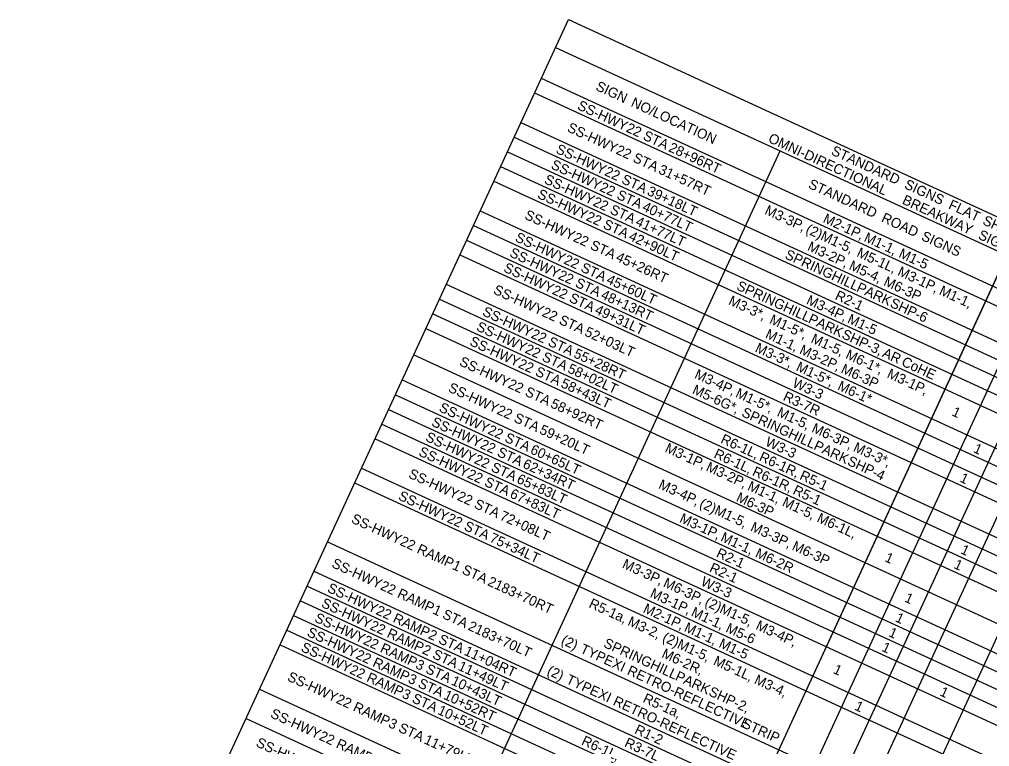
# Model space of a CAD drawing. Extents: x 627405 to 651306, y 367647 to 373471.
# Drawn here: x 650055.9 to 650493.4, y 373143.2 to 373471.4 of the extents above; entities that cross this region are included whole.
import ezdxf

# ---------------------------------------------------------------- set-up
doc = ezdxf.new("R2010")
doc.units = 0
doc.layers.add('Default', color=7, linetype='Continuous')

msp = doc.modelspace()

# ---------------------------------------------------------------- linework, layer by layer
at = {"layer": 'Default'}
for p, q in [((650055.92, 372934.12), (650303.5, 373471.4)), ((650303.5, 373471.4), (650303.5, 373471.4)), ((650303.5, 373471.4), (650631.25, 373320.37)), ((650297.69, 373458.78), (650625.43, 373307.75)), ((650291.26, 373444.83), (650619.01, 373293.81)), ((650291.26, 373444.83), (650597.76, 373303.6)), ((650288.2, 373438.19), (650615.95, 373287.16)), ((650282.08, 373424.91), (650609.83, 373273.88)), ((650279.02, 373418.27), (650606.77, 373267.24)), ((650157.2, 372887.45), (650398.97, 373412.11)), ((650275.96, 373411.63), (650603.71, 373260.6)), ((650272.9, 373404.99), (650600.65, 373253.96)), ((650269.84, 373398.35), (650597.59, 373247.32)), ((650263.72, 373385.06), (650591.46, 373234.03)), ((650260.66, 373378.42), (650588.4, 373227.39)), ((650257.6, 373371.78), (650585.34, 373220.75)), ((650254.54, 373365.14), (650582.28, 373214.11)), ((650259.47, 372840.32), (650501.24, 373364.98)), ((650259.47, 372840.32), (650498.03, 373358.01)), ((650248.42, 373351.86), (650576.16, 373200.83)), ((650275.41, 372832.97), (650513.97, 373350.66)), ((650245.35, 373345.22), (650573.1, 373194.19)), ((650288.03, 372827.16), (650526.59, 373344.85)), ((650242.29, 373338.57), (650570.04, 373187.54)), ((650300.65, 372821.34), (650539.21, 373339.03)), ((650239.23, 373331.93), (650566.98, 373180.9)), ((650321.24, 372811.86), (650559.79, 373329.55)), ((650233.73, 373319.98), (650561.47, 373168.95)), ((650228.52, 373308.69), (650556.27, 373157.66)), ((650225.46, 373302.05), (650553.21, 373151.02)), ((650222.4, 373295.41), (650550.15, 373144.38)), ((650219.34, 373288.76), (650547.09, 373137.74)), ((650216.28, 373282.12), (650544.03, 373131.09)), ((650210.16, 373268.84), (650537.91, 373117.81)), ((650207.1, 373262.2), (650534.85, 373111.17)), ((650194.86, 373235.63), (650522.61, 373084.6)), ((650188.74, 373222.35), (650516.49, 373071.32)), ((650185.68, 373215.71), (650513.43, 373064.68)), ((650182.62, 373209.07), (650510.37, 373058.04)), ((650179.56, 373202.43), (650507.3, 373051.4)), ((650176.5, 373195.79), (650504.24, 373044.76)), ((650173.44, 373189.14), (650501.18, 373038.12)), ((650164.26, 373169.22), (650492, 373018.19)), ((650158.13, 373155.94), (650485.88, 373004.91))]:
    msp.add_line(p, q, dxfattribs=at)

# ---------------------------------------------------------------- texts
for s, p in [('SIGN', (650315.43, 373439.68)), ('SS-HWY', (650307.16, 373431)), (' NO/LOCATION', (650329.81, 373433.05)), ('SS-HWY', (650302.57, 373421.04)), (' 22', (650327.6, 373421.58)), (' STA', (650335.24, 373418.06)), ('OMNI-DIRECTIONAL', (650393.22, 373416.21)), ('SS-HWY', (650297.45, 373411.32)), (' 28+96RT', (650346.81, 373412.73)), (' 22', (650323.01, 373411.62)), (' STA', (650330.65, 373408.1)), ('STANDARD', (650421.63, 373410.55)), ('SS-HWY', (650295.27, 373404.28)), (' 22', (650317.89, 373401.91)), (' 31+57RT', (650342.22, 373402.77)), ('SS-HWY', (650292.21, 373397.64)), (' 22', (650315.71, 373394.86)), (' STA', (650325.53, 373398.38)), ('STANDARD', (650411.3, 373395.5)), (' SIGNS', (650453.07, 373396.07)), ('SS-HWY', (650289.15, 373391)), (' STA', (650323.35, 373391.34)), (' 39+18LT', (650337.1, 373393.06)), (' 22', (650312.65, 373388.22)), (' BREAKWAY', (650452.12, 373389.07)), (' FLAT', (650472.97, 373386.9)), ('SS-HWY', (650283.33, 373381.6)), (' 22', (650309.59, 373381.58)), (' STA', (650320.29, 373384.7)), (' 40+77LT', (650334.91, 373386.01)), ('M3-3P,', (650391.64, 373383.71)), (' STA', (650317.23, 373378.06)), (' 41+77LT', (650331.85, 373379.37)), ('M2-1P,', (650417.92, 373379.97)), (' ROAD', (650442.73, 373381.01)), (' SHEET', (650488.39, 373379.79)), (' (2)M1-5,', (650408.62, 373375.89)), (' SIGNS', (650460.71, 373372.73)), (' SIGN', (650486.37, 373373.29)), ('SS-HWY', (650279.09, 373371.48)), (' 22', (650303.77, 373372.18)), (' STA', (650311.41, 373368.66)), (' 42+90LT', (650328.79, 373372.73)), (' M3-2P,', (650409.39, 373368.1)), (' M1-1,', (650434.89, 373372.14)), ('SS-HWY', (650276.56, 373364.59)), ('SPRINGHILL', (650400.73, 373363.73)), (' M5-1L,', (650431.62, 373365.29)), (' M1-5', (650450.53, 373364.94)), (' 22', (650299.53, 373362.06)), (' 45+26RT', (650322.98, 373363.33)), (' M5-4,', (650428.12, 373359.47)), ('SS-HWY', (650273.85, 373357.79)), (' 22', (650297, 373355.17)), (' STA', (650307.17, 373358.54)), (' M3-1P,', (650450.05, 373356.8)), (' STA', (650304.64, 373351.65)), (' 45+60LT', (650318.73, 373353.21)), (' M6-3P', (650443.76, 373352.27)), ('SS-HWY', (650269.26, 373347.83)), (' 22', (650294.29, 373348.37)), ('SPRINGHILL', (650378.94, 373349.62)), (' PARK', (650431.51, 373349.55)), (' M1-1,', (650468.78, 373348.17)), (' STA', (650301.93, 373344.85)), (' 48+13RT', (650316.21, 373346.32)), ('M3-3*,', (650375.31, 373342.93)), ('M3-4P,', (650410.43, 373343.16)), ('R2-1', (650423.36, 373345.25)), (' SHP-6', (650446.62, 373342.58)), ('SS-HWY', (650264.32, 373338.02)), (' 22', (650289.69, 373338.41)), (' 49+31LT', (650313.49, 373339.52)), (' STA', (650297.34, 373334.89)), (' M1-5*,', (650392.26, 373335.12)), (' PARK', (650409.73, 373335.43)), (' M1-5', (650427.41, 373335.34)), ('SS-HWY', (650261.61, 373331.22)), (' 52+03LT', (650308.9, 373329.56)), ('SS-HWY', (650258.55, 373324.58)), (' 22', (650284.76, 373328.61)), (' STA', (650292.4, 373325.09)), ('M1-1,', (650391.91, 373327.85)), (' M1-5,', (650410.96, 373326.5)), (' SHP-3,', (650424.84, 373328.47)), (' 22', (650282.04, 373321.81)), ('M3-3*,', (650387.33, 373321.6)), (' M3-2P,', (650405.78, 373321.46)), ('SS-HWY', (650253.91, 373315.44)), (' STA', (650289.68, 373318.28)), (' 55+28RT', (650303.96, 373319.76)), (' M6-1*,', (650426.59, 373319.3)), (' AR', (650443.1, 373320.05)), (' CoHE', (650451.8, 373316.04)), (' 22', (650278.98, 373315.16)), (' STA', (650286.62, 373311.64)), (' 58+02LT', (650301.25, 373312.96)), (' M1-5*,', (650404.27, 373313.79)), (' M6-3P', (650424.52, 373312.82)), ('M3-4P,', (650359.99, 373309.73)), (' M3-1P,', (650445.29, 373310.68)), ('SS-HWY', (650248.9, 373303.66)), (' 22', (650274.35, 373306.03)), (' 58+43LT', (650298.19, 373306.31)), ('M5-6G*,', (650358.99, 373302.76)), ('W3-3', (650404.14, 373305.8)), (' M6-1*', (650422.97, 373305.17)), (' STA', (650281.99, 373302.51)), (' M1-5*,', (650376.97, 373301.91)), ('R3-7R', (650399.92, 373299.69)), ('SS-HWY', (650244.77, 373294.7)), (' 22', (650269.34, 373294.24)), (' 58+92RT', (650293.56, 373297.18)), (' STA', (650276.98, 373290.72)), (' SPRINGHILL', (650379.69, 373293.22)), (' M1-5,', (650395.67, 373293.29)), ('1', (650476.05, 373292.79)), ('SS-HWY', (650241.37, 373288.21)), (' 22', (650265.21, 373285.28)), (' 59+20LT', (650288.55, 373285.39)), (' M6-3P,', (650411.3, 373286.09)), ('SS-HWY', (650238.65, 373281.41)), (' STA', (650272.85, 373281.76)), ('R6-1L,', (650371.77, 373280.46)), (' 22', (650261.81, 373278.8)), (' 60+65LT', (650284.42, 373276.43)), ('M3-1P,', (650346.67, 373276.42)), ('W3-3', (650391.9, 373279.23)), (' PARK', (650412.23, 373278.23)), (' M3-3*,', (650430.04, 373277.45)), ('1', (650485.74, 373276.25)), ('SS-HWY', (650235.59, 373274.77)), (' 22', (650259.09, 373272)), (' STA', (650269.45, 373275.28)), ('R6-1L,', (650368.71, 373273.82)), (' R6-1R,', (650387.6, 373273.17)), (' STA', (650266.73, 373268.47)), (' 62+34RT', (650281.01, 373269.95)), (' M3-2P,', (650363.64, 373268.6)), (' SHP-4', (650427.34, 373271.26)), ('SS-HWY', (650231, 373264.81)), (' 22', (650256.03, 373265.35)), (' R6-1R,', (650384.54, 373266.53)), (' R5-1', (650405.87, 373264.74)), ('1', (650479.62, 373262.97)), (' STA', (650263.67, 373261.83)), (' 65+83LT', (650278.3, 373263.15)), ('M3-4P,', (650343.74, 373259.96)), (' M1-1,', (650382.38, 373259.96)), ('SS-HWY', (650226.41, 373254.85)), (' 22', (650251.44, 373255.39)), (' 67+83LT', (650275.24, 373256.5)), ('M6-3P', (650378.79, 373254.18)), (' R5-1', (650402.81, 373258.1)), (' STA', (650259.08, 373251.87)), (' (2)M1-5,', (650360.71, 373252.14)), (' M1-5,', (650398.01, 373252.76)), (' 72+08LT', (650270.65, 373246.54)), (' M6-1L,', (650413.64, 373245.56)), ('SS-HWY', (650205.19, 373244.5)), (' 22', (650246.85, 373245.43)), (' STA', (650254.49, 373241.91)), ('M3-1P,', (650353.24, 373244.71)), (' M3-3P,', (650383.72, 373241.54)), (' M1-1,', (650370.22, 373236.89)), (' 22', (650225.63, 373235.08)), (' 75+34LT', (650266.06, 373236.58)), (' M6-3P', (650402.45, 373232.91)), (' RAMP', (650233.27, 373231.56)), ('R2-1', (650369.8, 373229.03)), (' M6-2R', (650385.85, 373229.69)), ('1', (650480, 373230.59)), ('SS-HWY', (650196.36, 373224.41)), (' 1', (650249.21, 373224.21)), ('M3-3P,', (650327.39, 373224.11)), ('1', (650445.76, 373227.04)), ('1', (650476.94, 373223.94)), (' STA', (650253.58, 373222.2)), ('R2-1', (650366.74, 373222.39)), (' 2183+70RT', (650265.15, 373216.87)), (' M6-3P,', (650344.36, 373216.29)), ('W3-3', (650362.83, 373216.14)), ('SS-HWY', (650194.38, 373213.25)), (' 22', (650216.79, 373215)), (' RAMP', (650224.44, 373211.48)), ('M3-1P,', (650339.94, 373210.89)), ('SS-HWY', (650191.67, 373206.45)), ('R5-1a,', (650312.35, 373206.27)), (' (2)M1-5,', (650363.1, 373207.66)), ('1', (650454.68, 373208.84)), (' 22', (650214.82, 373203.83)), (' 1', (650240.38, 373204.13)), (' STA', (650244.75, 373202.12)), ('M2-1P,', (650336.82, 373203.97)), (' M1-1,', (650356.92, 373203.07)), ('SS-HWY', (650188.64, 373199.79)), (' RAMP', (650222.46, 373200.31)), (' M3-2,', (650328.34, 373198.9)), ('1', (650450.55, 373199.87)), ('SS-HWY', (650185.24, 373193.31)), (' 22', (650212.11, 373197.03)), (' RAMP', (650219.75, 373193.51)), (' 2183+70LT', (650256.31, 373196.79)), (' M1-1,', (650353.79, 373196.15)), (' M5-6', (650372.55, 373195.87)), (' M3-4P,', (650386.1, 373197.06)), ('1', (650447.49, 373193.23)), (' 22', (650209.08, 373190.37)), (' 2', (650238.41, 373192.96)), (' STA', (650242.98, 373190.85)), ('(2)', (650299.81, 373189.75)), ('SPRINGHILL', (650318.97, 373188.35)), (' (2)M1-5,', (650343.97, 373191.7)), (' M1-5', (650369.43, 373188.95)), ('SS-HWY', (650182.52, 373186.51)), (' RAMP', (650216.72, 373186.85)), (' 2', (650235.69, 373186.16)), (' 11+04RT', (650254.55, 373185.52)), (' TYPE', (650306.89, 373186.49)), ('M6-2R,', (650345.19, 373183.7)), ('1', (650444.43, 373186.59)), (' 22', (650205.68, 373183.89)), (' RAMP', (650213.32, 373180.37)), (' STA', (650240.27, 373184.05)), (' XI', (650321.24, 373179.87)), (' M5-1L,', (650366.97, 373181.1)), (' 22', (650202.96, 373177.09)), (' 3', (650232.67, 373179.5)), (' STA', (650237.17, 373177.43)), (' 11+49LT', (650251.83, 373178.72)), ('(2)', (650293.46, 373175.95)), (' RETRO-REFLECTIVE', (650328.09, 373176.72)), ('1', (650422.5, 373176.57)), ('SS-HWY', (650176.4, 373173.22)), (' RAMP', (650210.6, 373173.57)), (' 3', (650229.26, 373173.02)), (' 10+43LT', (650248.74, 373172.1)), (' TYPE', (650300.53, 373172.69)), (' PARK', (650349.75, 373174.17)), (' M3-4,', (650385.4, 373172.6)), (' STA', (650233.76, 373170.95)), (' SHP-2,', (650364.86, 373167.2)), ('1', (650470.59, 373166.48)), (' 22', (650196.84, 373163.81)), (' 3', (650226.55, 373166.22)), (' STA', (650231.05, 373164.14)), (' 10+52RT', (650245.33, 373165.62)), (' XI', (650314.88, 373166.08)), (' RETRO-REFLECTIVE', (650321.74, 373162.92)), ('R5-1a,', (650336.7, 373163.46)), (' RAMP', (650204.48, 373160.28)), (' 10+52LT', (650242.62, 373158.81)), ('1', (650432.19, 373160.03)), ('SS-HWY', (650168.75, 373156.62)), (' 3', (650220.43, 373152.94)), (' STA', (650224.93, 373150.86)), ('R1-2', (650332.98, 373149.38)), (' STRIP', (650379.88, 373152.85)), (' 22', (650189.19, 373147.2)), (' 11+79LT', (650236.49, 373145.53)), ('R6-1L,', (650309.03, 373144.31)), ('SS-HWY', (650162.28, 373143.5)), (' RAMP', (650196.83, 373143.68)), ('R3-7L', (650328.4, 373143.44))]:
    msp.add_text(s, height=4.5, rotation=335.2593, dxfattribs=at).set_placement(p)

doc.saveas('drawing.dxf')
